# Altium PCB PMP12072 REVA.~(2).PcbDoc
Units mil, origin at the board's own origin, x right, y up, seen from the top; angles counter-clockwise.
Board outline 4950 x 3450 mil, 2 copper layers (Top Layer, Bottom Layer), stack 62 mil thick; 20 components, 17 nets, 97 pads, 14 vias.
Unrouted connection lines stored in the file: 46.
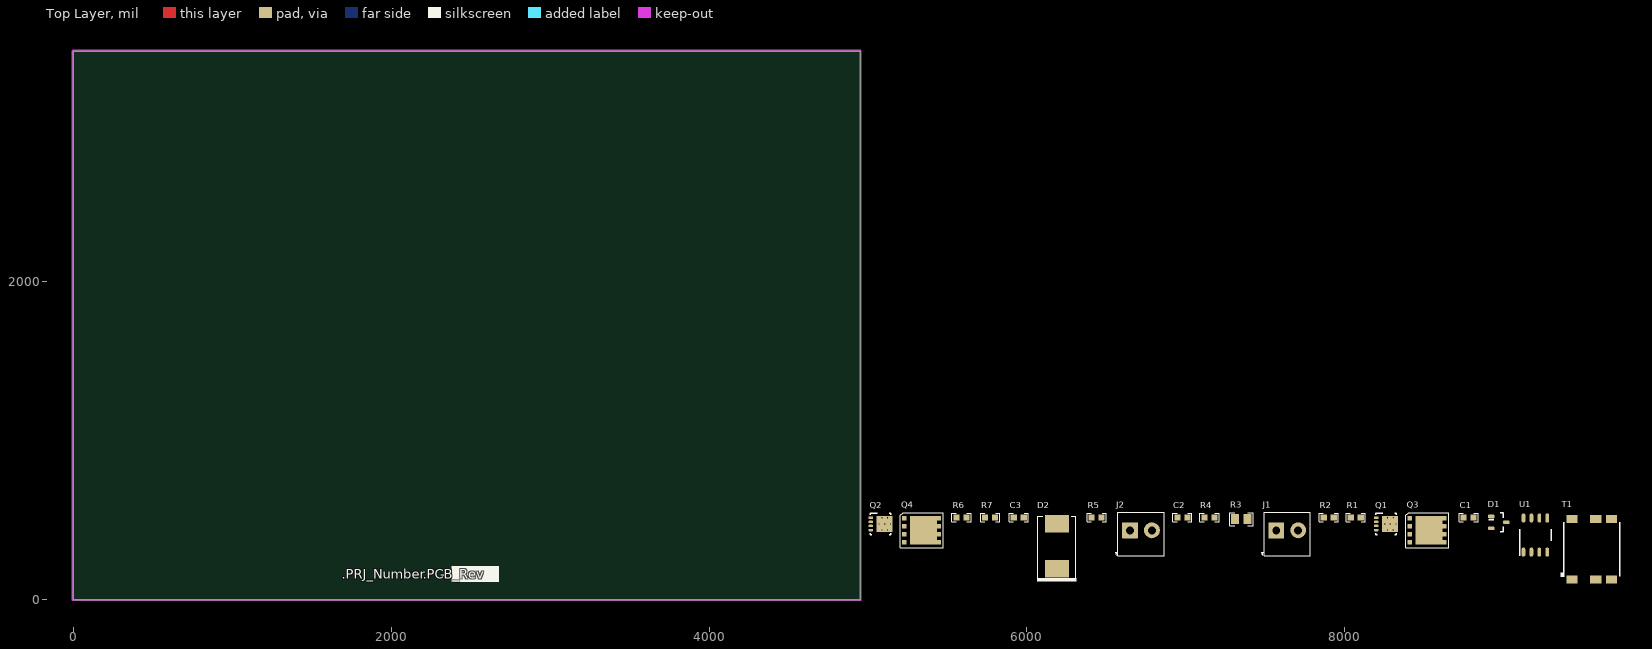
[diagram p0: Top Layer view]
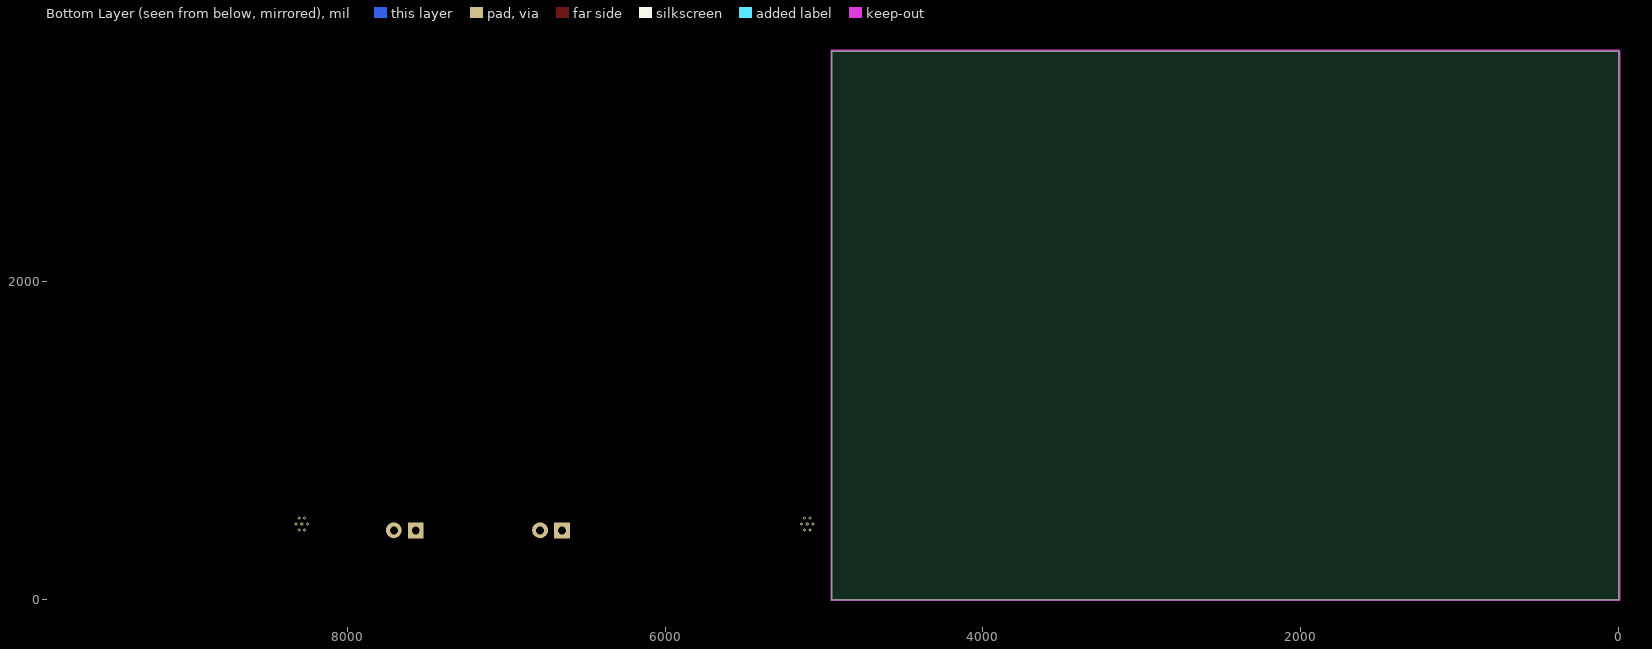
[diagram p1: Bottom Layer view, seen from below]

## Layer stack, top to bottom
Top Solder: solder mask 0.4, Solder Resist, Dk 3.5
Top Layer: signal copper 1.4
Dielectric1: core 59.2, FR-4, Dk 4.8
Bottom Layer: signal copper 1.4
Bottom Solder: solder mask 0.4, Solder Resist, Dk 3.5

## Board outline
0,0 4950,0 4950,3450 0,3450

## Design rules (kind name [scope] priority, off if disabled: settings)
AcuteAngle [All] p1: minimum=4.50000000000000E+0001 checktracksonly=FALSE
AssemblyTestPointUsage [All] p1: valid=2
Clearance Clearance_BoardEdge_MountingHoles [OnCopper and InComponentClass('Mounting Holes') vs IsKeepOut] p1: gap=40
Clearance Clearance_BoardEdge_Poly [OnCopper and InPoly vs IsKeepOut] p2: gap=25
Clearance Clearance_BoardEdge [OnCopper and Not InComponentClass('Logo') and not InComponentClass('FiducialMark') and not InRegion(1000,500,4000,800) and Not IsKeepout vs IsKeepOut] p3: gap=75
Clearance Clearance_Poly [InPolygon] p4: gap=25
Clearance [All] p5: gap=7.87
ComponentClearance ComponentClearance_Shunt [InComponentClass('Header') vs InComponentClass('Shunt')] p1: gap=0 collisioncheckmode=3 verticalgap=0 showdistances=FALSE
ComponentClearance ComponentClearance_MountingHoles_FiducialMarks [InComponentClass('Mounting Holes') vs InComponentClass('FiducialMark')] p2: gap=50 collisioncheckmode=3 verticalgap=10 showdistances=FALSE
ComponentClearance ComponentClearance_Logo [InComponentClass('Logo')] p3: gap=50 collisioncheckmode=3 verticalgap=10 showdistances=FALSE
ComponentClearance ComponentClearance_ScrewToNut [(HasFootprint('NY PMS 440 0025 PH')) vs (HasFootprint('Keystone_1902C'))] p4: gap=5 collisioncheckmode=3 verticalgap=10 showdistances=FALSE
ComponentClearance ComponentClearance_MountingHoles [InComponentClass('Mounting Holes')] p5: gap=250 collisioncheckmode=3 verticalgap=100000 showdistances=FALSE
ComponentClearance ComponentClearance_SmallPassives [HasFootprint('0201*') or HasFootprint('0402*') or HasFootprint('0508') or HasFootprint('0603*') or HasFootprint('0612') or HasFootprint('0805*') or HasFootprint('0815*') or HasFootprint('0830*') or HasFootprint('1206*') or HasFootprint('1210*') or HasFootprint('1808*') or HasFootprint('1812*') or HasFootprint('1825*') or HasFootprint('2010*') or HasFootprint('2220*') or HasFootprint('2225*') or HasFootprint('2512*') or HasFootprint('2728*') or HasFootprint('3518*') vs HasFootprint('0201*') or HasFootprint('0402*') or HasFootprint('0508') or HasFootprint('0603*') or HasFootprint('0612') or HasFootprint('0805*') or HasFootprint('0815*') or HasFootprint('0830*') or HasFootprint('1206*') or HasFootprint('1210*') or HasFootprint('1808*') or HasFootprint('1812*') or HasFootprint('1825*') or HasFootprint('2010*') or HasFootprint('2220*') or HasFootprint('2225*') or HasFootprint('2512*') or HasFootprint('2728*') or HasFootprint('3518*')] p6: gap=20 collisioncheckmode=3 verticalgap=10 showdistances=FALSE
ComponentClearance ComponentClearance_THtoSMT [IsThruComponent vs IsSMTComponent] p7: gap=100 collisioncheckmode=3 verticalgap=30 showdistances=FALSE
ComponentClearance ComponentClearance_THtoTH [IsThruComponent vs IsThruComponent] p8: gap=118.11 collisioncheckmode=3 verticalgap=30 showdistances=FALSE
ComponentClearance [All] p9: gap=40 collisioncheckmode=3 verticalgap=10 showdistances=FALSE
DiffPairsRouting [All] p1: maxlimit=100 minlimit=10 mostfreqgap=10 toplayer_minwidth=15 toplayer_maxwidth=15 toplayer_prefwidth=15 bottomlayer_minwidth=15 bottomlayer_maxwidth=15 bottomlayer_prefwidth=15 maxuncoupledlength=1000
FabricationTestPointUsage TestPointUsage [All] p1: valid=2 allowmultiple=FALSE
FabricationTestpoint Testpoint [All] p1: side=3 testpointundercomponent=TRUE minsize=40 maxsize=100 preferedsize=60 minholesize=0 maxholesize=40 preferedholesize=32 testpointgrid=1 allowsidetop=TRUE allowsidebottom=TRUE usegrid=TRUE gridtolerance=0.01
FanoutControl Fanout_LCC [IsLCC] p1: bgadir=Out bgaviamode=Centered fanoutstyle=Auto fanoutdirection=Alternating viagrid=1 // Fanout_LCC (Default Rule)
FanoutControl Fanout_BGA [IsBGA] p2: bgadir=Out bgaviamode=Centered fanoutstyle=Auto fanoutdirection=Alternating viagrid=1 // Fanout_BGA (Default Rule)
FanoutControl Fanout_Default [All] p4: bgadir=Out bgaviamode=Centered fanoutstyle=Auto fanoutdirection=Alternating viagrid=1 // Fanout_Default (Default Rule)
FanoutControl Fanout_Small [(CompPinCount < 5)] p5: bgadir=Out bgaviamode=Centered fanoutstyle=Auto fanoutdirection=OutThenIn viagrid=1 // Fanout_Small (Default Rule)
HoleSize [All] p1: absolutevalues=TRUE maxlimit=251 minlimit=8 maxpercent=80.000 minpercent=20.000
MinimumAnnularRing MinimumAnnularRing_ThermalPadVias [IsVia and InAnyComponent] p1: minimumring=5.91
MinimumAnnularRing [All] p2: minimumring=9
MinimumSolderMaskSliver MinimumSolderMaskSliver_Logo [InComponentClass('Logo') vs InComponentClass('Logo')] p1: minsoldermaskwidth=0.7
MinimumSolderMaskSliver [All] p2: minsoldermaskwidth=3.94
PlaneConnect [All] p1: planeconnectstyle=Relief reliefexpansion=10 reliefentries=4 reliefconductorwidth=10 reliefairgap=10
PolygonConnect [All] p1: connectstyle=Relief reliefconductorwidth=10 reliefentries=4 polygonreliefangle="90 Angle" airgapwidth=10
RoutingVias ThermalPadVias [IsVia and InAnyComponent] p1: holewidth=7.87 width=19.68 viastyle="Through Hole" minholewidth=7.87 minwidth=19.68 maxholewidth=12.99 maxwidth=23.62
RoutingVias [All] p2: holewidth=16 width=34 viastyle="Through Hole" minholewidth=7.87 minwidth=26 maxholewidth=40 maxwidth=65
SMDToCorner [All] p1: distance=30000
SilkToSilkClearance [All] p1: silktosilkclearance=5
SilkToSolderMaskClearance SilkscreenOverComponentPads [IsPad] p1: minsilkscreentomaskgap=5 clearancetoexposedcopper=TRUE
SolderMaskExpansion [All] p1: expansion=1.97
UnpouredPolygon [All] p1: allowunpoured=FALSE
Width [All] p1: maxlimit=100 minlimit=6 preferedwidth=10 checkconnectedcopper=TRUE
15 further rules are at their usual default settings.

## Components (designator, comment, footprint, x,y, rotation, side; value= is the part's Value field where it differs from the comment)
C1 "C1608X7R1H104K" 0603 8778,516 r0 top
C2 "C1608X7R1H103K" 0603 6978,516 r0 top
C3 "C1608X5R1C105K" 0603 5948,516 r0 top
D1 "BAT54C" SOT-23 8968,486 r0 top
D2 "SMCJ48CA" SMC 6188,336 r90 top
J1 "ED555/2DS" TERM_BLK_ED555-2DS 7568,436 r0 top
J2 "ED555/2DS" TERM_BLK_ED555-2DS 6648,436 r0 top
Q1 "CSD19538Q3A" DNH0008A 8258,476 r0 top
Q2 "CSD19538Q3A" DNH0008A 5078,476 r0 top
Q3 "ALT" TRANS_NexFET_Q5A 8518,436 r0 top
Q4 "ALT" TRANS_NexFET_Q5A 5338,436 r0 top
R1 "CRCW060310K0FKEA" 0603 8068,516 r0 top
R2 "CRCW06033R30JNEA" 0603 7898,516 r0 top
R3 "CRCW0805301RFKEA" 0805_HV 7348,506 r0 top
R4 "CRCW0603100KFKEA" 0603 7148,516 r0 top
R5 "CRCW06031K00FKEA" 0603 6438,516 r0 top
R6 "CRCW060320K0FKEA" 0603 5588,516 r0 top
R7 "CRCW060380K6FKEA" 0603 5768,516 r0 top
T1 "PA0173NLT" PULSE_PA0173 9568,316 r90 top
U1 "UCC28086D" D0008A_N 9198,406 r90 top

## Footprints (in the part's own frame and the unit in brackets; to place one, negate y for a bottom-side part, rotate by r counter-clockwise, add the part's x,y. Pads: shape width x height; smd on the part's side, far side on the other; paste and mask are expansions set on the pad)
0603 [mm] "0603 from SM-752 data"
  rect 1x0.95 smd: 1(-0.8,0) 2(0.8,0)
  silkscreen extent -1.52,-0.69 1.52,0.69, body extent -0.87,-0.47 0.87,0.47, height 1
0805_HV [mil] "0805 with 30mil clearance between pads"
  rect 50x63 smd: 1(-40,0) 2(40,0)
  silkscreen extent -74,-40 74,40, body extent -43,-29 43,29, height 57
D0008A_N [mm] "SOIC, 8-Leads, Body 4.9x3.9mm, Pitch 1.27mm, IPC Medium Density"
  oval 1.45x0.6 smd: 1(-2.725,1.905) 2(-2.725,0.635) 3(-2.725,-0.635) 4(-2.725,-1.905) 5(2.725,-1.905) 6(2.725,-0.635) 7(2.725,0.635) 8(2.725,1.905)
  silkscreen extent -3.3,-2.5 0.9,2.5, body extent -3,-2.45 3,2.45, height 1.63
DNH0008A [mm] "8 pin VSONP, 0.65 mm pitch"
  rrect50% 0.7x0.4 smd paste-0.05 mask-0.05: 1(-1.55,0.975) 2(-1.55,0.325) 3(-1.55,-0.325) 4(-1.55,-0.975) 5(1.55,-0.975) 6(1.55,-0.325) 7(1.55,0.325) 8(1.55,0.975)
  rrect14% 0.705x1.125 on Top Paste: 9(-0.208,-0.663) 9(-0.208,0.662) 9(0.697,-0.663) 9(0.697,0.662)
  rrect6% 1.775x2.45 on Top Solder: 9(0.327,0)
  rrect4% 2.51x2.55 smd paste-1.5 mask-1.5: 9(0.645,0)
  rect 0.5x0.3 on Top Solder: 9(1.175,-0.975) 9(1.175,-0.325) 9(1.175,0.325) 9(1.175,0.975)
  silkscreen extent -1.62,-1.7 1.62,1.7, body extent -1.65,-1.65 1.65,1.66, height 0.91
PULSE_PA0173 [mil] "PULSE"
  rect 50x70 smd: 1(-190,140) 2(-190,-10) 3(-190,-110) 4(190,-110) 5(190,-10) 6(190,140)
  silkscreen extent -175,-160 170,211, body extent -235,-160 235,190, height 160
SMC [mil] "Molded Diode, 2-Leads, Body 6.9x5.8mm, IPC Medium Density, based on OnSemi component dimensions and land patterns"
  rect 110x150 smd: 1(-140.49,0) 2(140.49,0)
  silkscreen extent -221,-124 189,123, body extent -156,-116 156,116, height 91
SOT-23 [mm] "SOT23, 3-Leads, Body 2.9x1.3mm, Pitch 0.95mm, Lead Span 2.5mm, IPC Medium Density"
  rrect50% 1x0.6 smd: 1(-1.2,0.95) 2(-1.2,-0.95) 3(1.2,0)
  silkscreen extent -1.63,-1.5 0.7,1.5, body extent -1.16,-1.45 1.21,1.45, height 1
TERM_BLK_ED555-2DS [mil]
  rrect4% 100x100 hole 50: 1(0,0)
  round 100 hole 50: 2(138,0)
  silkscreen extent -93,-161 215,113, body extent -69,-150 207,106, height 323
TRANS_NexFET_Q5A [mm] "TI recommended land pattern (nominal) M0139-01"
  rect 0.75x0.675 smd paste-0.1 mask+0.051: 1(-2.776,1.917) 2(-2.776,0.639) 3(-2.776,-0.639) 4(-2.776,-1.917)
  rect 0.655x0.675 smd paste-0.1 mask+0.051: 5(2.776,-1.917) 6(2.776,-0.639) 7(2.776,0.639) 8(2.776,1.917)
  rect 4.295x4.51 smd paste-2.2 mask+0.051: 9(0.301,0)
  silkscreen extent -3.4,-2.8 3.4,2.8, body extent -3.05,-2.5 3.05,2.5, height 1.11

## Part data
C1: "CAP, CERM, 0.1uF, 50V, +/-10%, X7R, 0603"
C2: "CAP, CERM, 0.01uF, 50V, +/-10%, X7R, 0603"
C3: "CAP, CERM, 1uF, 16V, +/-10%, X5R, 0603"
D1: library part BAT54C-7-F, "Diode, Schottky, 30V, 0.2A, SOT-23"
D2: library part SMCJ33CA, "Diode, TVS, Bi, 48V, 1500W, SMC"
J1 J2: "Terminal Block, 6A, 3.5mm Pitch, 2-Pos, TH"
Q1 Q2: "MOSFET, N-CH, 100 V, 5 A, DNH0008A"
Q3 Q4: library part CSD19534Q5A, "MOSFET, SON 5x6mm"
R1: "RES, 10.0 k, 1%, 0.1 W, 0603"
R2: "RES, 3.3 ohm, 5%, 0.1W, 0603"
R3: "RES, 301 ohm, 1%, 0.125W, 0805"
R4: "RES, 100k ohm, 1%, 0.1W, 0603"
R5: "RES, 1.00 k, 1%, 0.1 W, 0603"
R6: "RES, 20.0 k, 1%, 0.1 W, 0603"
R7: "RES, 80.6 k, 1%, 0.1 W, 0603"
T1: "Transformer, Gate Drive, 980uH, SMT"
U1: "Push-Pull PWM Controller with Programmable Slope Compensation with Current Control, 50 % Duty Cycle, -40 to +85 degC, 8-pin SOIC (D), Green (RoHS & no Sb/Br)"

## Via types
v1: diameter 19.68, hole 7.87, Top Layer to Bottom Layer, 14 vias

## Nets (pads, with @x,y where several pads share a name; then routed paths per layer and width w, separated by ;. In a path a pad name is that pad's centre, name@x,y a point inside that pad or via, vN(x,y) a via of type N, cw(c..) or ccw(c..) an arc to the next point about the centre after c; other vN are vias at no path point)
GND: C3.1 J1.2 R5.2 R6.2 R7.2 U1.5
NetC1_1: C1.1 U1.6
NetC1_2: C1.2 T1.1
NetC2_1: C2.1 D1.3 R2.2 R4.2
NetC2_2: C2.2 Q1.1 Q1.2 Q1.3 Q2.1 Q2.2 Q2.3 Q3.1 Q3.2 Q3.3 Q4.1 Q4.2 Q4.3 R4.1 T1.3 T1.5
NetC3_2: C3.2 R1.2 R3.2 U1.8
NetD1_1: D1.1 T1.2
NetD1_2: D1.2 T1.4
NetD2_1: D2.1 J2.1 Q1.5 Q1.6 Q1.7 Q1.8 Q1.9@8283.39,476 Q3.5 Q3.6 Q3.7 Q3.8 Q3.9
  other v1: 8267.65,437.61 8303.28,437.61 8249.83,476 8285.46,476 8321.09,476 8267.65,514.39 8303.28,514.39
NetD2_2: D2.2 J2.2 Q2.5 Q2.6 Q2.7 Q2.8 Q2.9@5103.39,476 Q4.5 Q4.6 Q4.7 Q4.8 Q4.9
  other v1: 5087.65,437.61 5123.28,437.61 5069.83,476 5105.46,476 5141.09,476 5087.65,514.39 5123.28,514.39
NetJ1_1: J1.1 R3.1
NetQ1_4: Q1.4 Q2.4 Q3.4 Q4.4 R2.1
NetR1_1: R1.1 U1.1
NetR5_1: R5.1 U1.3
NetR6_1: R6.1 U1.2
NetR7_1: R7.1 U1.4
NetT1_6: T1.6 U1.7
pads on no net: Q1.9@8249.83,449.92 Q1.9@8249.83,502.08 Q1.9@8270.89,476 Q1.9@8285.46,449.92 Q1.9@8285.46,502.08 Q1.9@8304.26,437.61 Q1.9@8304.26,463.2 Q1.9@8304.26,488.8 Q1.9@8304.26,514.39 Q2.9@5069.83,449.92 Q2.9@5069.83,502.08 Q2.9@5090.89,476 Q2.9@5105.46,449.92 Q2.9@5105.46,502.08 Q2.9@5124.26,437.61 Q2.9@5124.26,463.2 Q2.9@5124.26,488.8 Q2.9@5124.26,514.39

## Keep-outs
Keep-Out Layer:
  lines w10: -5,0 ccw(c0,0) 0,-5 ; -5,0 ccw(c0,0) 0,-5 ; -5,0 ccw(c0,0) 0,-5 ; -5,0 ccw(c0,0) 0,-5 ; -5,0 ccw(c0,0) 0,-5 ; -5,0 ccw(c0,0) 0,-5 ; -5,0 -5,3450 ; -5,3450 cw(c0,3450) 0,3455 ; -5,3450 cw(c0,3450) 0,3455 ; -5,3450 cw(c0,3450) 0,3455 ; -5,3450 cw(c0,3450) 0,3455 ; -5,3450 cw(c0,3450) 0,3455 ; -5,3450 cw(c0,3450) 0,3455 ; 0,-5 4950,-5 ; 0,3455 4950,3455 ; 4950,-5 ccw(c4950,0) 4955,0 ; 4950,-5 ccw(c4950,0) 4955,0 ; 4950,-5 ccw(c4950,0) 4955,0 ; 4950,-5 ccw(c4950,0) 4955,0 ; 4950,-5 ccw(c4950,0) 4955,0 ; 4950,-5 ccw(c4950,0) 4955,0 ; 4950,3455 cw(c4950,3450) 4955,3450 ; 4950,3455 cw(c4950,3450) 4955,3450 ; 4950,3455 cw(c4950,3450) 4955,3450 ; 4950,3455 cw(c4950,3450) 4955,3450 ; 4950,3455 cw(c4950,3450) 4955,3450 ; 4950,3455 cw(c4950,3450) 4955,3450 ; 4955,0 4955,3450
  text ".Layer_Name" at 577,-858.49 h60

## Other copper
Top Layer:
  text ".Layer_Name" at 577,-858.49 h60
Bottom Layer:
  text ".Layer_Name" at 577,-858.49 h60

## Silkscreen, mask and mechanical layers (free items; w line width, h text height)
Top Overlay:
  region: 2680,210 2380,210 2380,110 2680,110
  text ".PRJ_Number" at 1690,130 h60
  text ".PCB_Rev" at 2200,130.01 h60
  text "-" at 2310,130.01 h60
  text ".Layer_Name" at 577,-858.49 h60
Bottom Overlay:
  text ".Layer_Name" at 577,-858.49 h60
Top Paste:
  text ".Layer_Name" at 577,-858.49 h60
Bottom Paste:
  text ".Layer_Name" at 577,-858.49 h60
Top Solder:
  text ".Layer_Name" at 577,-858.49 h60
  text ".Layer_Name" at 577,-858.49 h60
Bottom Solder:
  text ".Layer_Name" at 577,-858.49 h60
Drill Guide:
  text ".Layer_Name" at 577,-858.49 h60
M1 Board Outline:
  the board outline again, w10
  text ".Layer_Name" at 577,-858.49 h60
M2 Board Dimensions:
  rectangle: 125,-410.5 500,-285.5
  rectangle: 0,-285.5 125,-160.5
  lines w7: 0,-285.5 1000,-285.5 ; 125,-410.5 125,-160.5 ; 250,-410.5 250,-160.5 ; 500,-410.5 500,-160.5 ; 750,-410.5 750,-160.5 ; 0,-410.5 0,-160.5 1000,-160.5 1000,-410.5 0,-410.5
  text ".Layer_Name" at 577,-858.49 h60
M3 3D STEP Top:
  text ".Layer_Name" at 577,-858.49 h60
M4 3D STEP Bottom:
  text ".Layer_Name" at 577,-858.49 h60
M5 Assembly Top:
  lines w10: -292,-930.17 6308,-930.17 ; -292,-726.83 6310,-726.83 ; -292,-523.5 -292,-1133.5 3713,-1133.5 6310,-1133.5 6310,-523.5 -291.5,-523.5 -291.5,-1133.5 1284,-1133.5 ; 2173,-1133.5 2173,-523.5 ; 3440,-726.83 3440,-523.5 ; 4280,-726.83 4280,-523.5 ; 4902,-1140 4902,-937.17
  text "COMPONENTS MARKED 'DNP' SHOULD NOT BE POPULATED." at 1153.5,-318.5 h60
  text "ASSEMBLY VARIANT:" at 1153,-434 h60
  text ".VariantName" at 2189,-434 h60
  text "PCB VIEWED FROM TOP SIDE" at -228.5,-655.67 h60
  text "BOARD #:" at 2248,-655.67 h60
  text ".PRJ_Number" at 2793.5,-655.67 h60
  text "REV:" at 3638,-655.67 h60
  text ".PCB_Rev" at 3929.5,-655.67 h60
  text "SVN REV:" at 4476,-655.67 h60
  text ".VersionControl_RevNumber" at 4982,-655.67 h60
  text "IGNORE ->" at -228.5,-858.49 h60
  text "PLOT NAME =" at -228.5,-1064.34 h60
  text ".plot_File_Name" at 577,-1064.34 h60
  text "GENERATED    :" at 2250,-1064.34 h60
  text ".Print_Date" at 3119.5,-1064.34 h60
  text ".Print_Time" at 3848.5,-1064.34 h60
  text "TEXAS INSTRUMENTS" at 5113,-1064.34 h60
M6 Assembly Bottom:
  lines w10: -292.5,-727.33 6309.5,-727.33 ; -290.5,-930.67 6309.5,-930.67 ; 1115.5,-1140.5 1115.5,-937.67 ; 1737.5,-727.33 1737.5,-524 ; 2577.5,-727.33 2577.5,-524 ; 3844.5,-1134 3844.5,-524 ; 4733.5,-1134 6309,-1134 6309,-524 -292.5,-524 -292.5,-1134 2304.5,-1134 6309.5,-1134 6309.5,-524
  text "COMPONENTS MARKED 'DNP' SHOULD NOT BE POPULATED." at 6102,-318 h60
  text ".VariantName" at 5058,-434 h60
  text "ASSEMBLY VARIANT:" at 6097,-434 h60
  text ".VersionControl_RevNumber" at 1035.5,-656.17 h60
  text "SVN REV:" at 1541.5,-656.17 h60
  text ".PCB_Rev" at 2088,-656.17 h60
  text "REV:" at 2379.5,-656.17 h60
  text ".PRJ_Number" at 3224,-656.17 h60
  text "BOARD #:" at 3769.5,-656.17 h60
  text "PCB VIEWED FROM BOTTOM SIDE" at 6246,-656.17 h60
  text "IGNORE ->" at 2547.85,-858.49 h60
  text "TEXAS INSTRUMENTS" at 904.5,-1064.84 h60
  text ".Print_Time" at 2169,-1064.84 h60
  text ".Print_Date" at 2898,-1064.84 h60
  text "GENERATED    :" at 3767.5,-1064.84 h60
  text ".plot_File_Name" at 5440.5,-1064.84 h60
  text "PLOT NAME =" at 6246,-1064.84 h60
M9 Title Sheet:
  drawing of 57 lines, arcs and shapes, not listed
  text "1" at 739.84,8036.5 h70
  text "2" at 3235.5,8036.5 h70
  text "3" at 5724.84,8036.5 h70
  text "4" at 8231.51,8036.5 h70
  text "5" at 10730.5,8036.5 h70
  text "6" at 13235.5,8036.5 h70
  text "A" at -416.5,6893.5 h70
  text "A" at 14383.5,6893.5 h70
  text "B" at -416.5,4513.5 h70
  text "B" at 14383.5,4513.5 h70
  text "C" at -416.5,2138.5 h70
  text "C" at 14383.5,2138.5 h70
  text "PROJECT TITLE:" at 11343.5,277.5 h45
  text ".PRJ_Title" at 11393.5,144.17 h70
  text "DESIGNED FOR:" at 11343.5,-23.5 h45
  text ".PRJ_Customer" at 11393.5,-163.5 h70
  text "D" at -416.5,-231.5 h70
  text "D" at 14383.5,-231.5 h70
  text "FILE NAME:" at 11343.5,-323.5 h45
  text ".PCB_File_Name_No_Path" at 11393.5,-443.5 h70
  text "Texas Instruments (TI) and/or its licensors do not warrant the accuracy or completeness of this specification" at 6374,-605.34 h45
  text "ENGINEER:" at 11343.5,-613.5 h45
  text "LAYOUT BY:" at 12848.5,-613.5 h45
  text "or any information contained therein. TI and/or its licensors do not warrant that this design will meet" at 6329.01,-718 h45
  text ".PRJ_Engineer" at 11393.5,-768.49 h70
  text ".PCB_Layout" at 12899,-768.49 h70
  text "the specifications, will be suitable for your application or fit for any particular purpose, or will operate in" at 6329.01,-830.67 h45
  text ".Layer_Name" at 577,-858.49 h60
  text "ALTIUM DESIGNER VERSION:" at 12848.5,-923.5 h45
  text "an implementation. TI and/or its licensors do not warrant that the design is production worthy. You should" at 6329.01,-943.33 h45
  text "completely validate and test your design implementation to confirm the system functionality for your application." at 6374,-1056 h45
  text ".print_Scale" at 11393.5,-1056.83 h70
  text ".Application_BuildNumber" at 12899,-1056.83 h70
  text "1" at 739.84,-1263.5 h70
  text "2" at 3235.5,-1263.5 h70
  text "3" at 5724.84,-1263.5 h70
  text "4" at 8231.51,-1263.5 h70
  text "5" at 10730.5,-1263.5 h70
  text "6" at 13235.5,-1263.5 h70
M10 Fab Notes:
  drawing of 185 lines, arcs and shapes, not listed
  text "DESIGN INFORMATION" at 12381.02,5910 h60
  text "MIN. TRACK WIDTH:" at 11736.46,5730 h60
  text "8" at 12832.7,5730 h60
  text "MIL" at 12987.46,5730 h60
  text "MIN. CLEARANCE:" at 11736.46,5598 h60
  text "0.2" at 12772.7,5598 h60
  text "mm" at 12987.46,5598 h60
  text "MIN. VIA PAD SIZE:" at 11736.46,5466 h60
  text "24" at 12802.71,5466 h60
  text "MIL" at 12987.46,5466 h60
  text "0.05mm (2MIL)" at 12431.46,5324.29 h60
  text "MINIMUM ANNULAR RING" at 11407.23,5320 h60
  text "EXTERNAL" at 13139.46,5320 h60
  text "PER" at 11607.23,5202 h60
  text "IPC-D-275 CLASS 2 LEVEL C" at 11827.23,5202 h60
  text "MIL, HOLES" at 13315.46,5089.71 h60
  text "+/-" at 12923,5089 h60
  text "+/-" at 13777,5089 h60
  text "REGISTRATION TOLERANCES:" at 11407.23,5084 h60
  text "METAL" at 12607,5084 h60
  text "5" at 13183.2,5084 h60
  text "3" at 14016.2,5084 h60
  text "MIL" at 14132.46,5084 h60
  text "MATERIAL:" at 11332.46,4874.54 h60
  text "FR-4 High Tg" at 12318.9,4734.21 h60
  text "FR-408" at 11753.46,4725.64 h60
  text "X" at 12165.46,4725.64 h60
  text "OTHER" at 13241.46,4725.64 h60
  text "62 MIL (1.6mm) +/-10%" at 12073.56,4562.92 h60
  text "THICKNESS:" at 11407.23,4558.64 h60
  text "X" at 11945.4,4558.64 h60
  text "OTHER" at 13358.46,4558.64 h60
  text "TOLERANCE:" at 11407.23,4400.64 h60
  text "X" at 12246.53,4400.64 h60
  text "ANSI IPC-6012 TYPE 3 CLASS 2" at 12433.48,4400.64 h60
  text "OTHER +/-" at 12433.46,4244.64 h60
  text "BOW & TWIST:" at 11407.23,4087.64 h60
  text "X" at 12246.53,4087.64 h60
  text "ANSI IPC-6012 TYPE 3 CLASS 2" at 12433.48,4087.64 h60
  text "OTHER +/-" at 12433.46,3929.13 h60
  text "DRILLING:" at 11332.46,3790.64 h60
  text "REFERENCE:" at 11407.23,3673.64 h60
  text "X" at 12055.46,3673.64 h60
  text "AS SHOWN" at 12242.46,3673.64 h60
  text "X" at 12956.46,3673.64 h60
  text "NC_DRILL FILES" at 13093.46,3673.64 h60
  text "PTH MIN COPPER THICKNESS:" at 11407.23,3515.64 h60
  text "X" at 12757.46,3515.64 h60
  text "1MIL" at 12894.46,3515.64 h60
  text "OTHER" at 13391.46,3515.64 h60
  text "BOARD FINISH:" at 11332.46,3356.64 h60
  text "SILKSCREEN:" at 11487.68,3238.64 h60
  text "X" at 12436.46,3238.64 h60
  text "TOP" at 12562.46,3238.64 h60
  text "X" at 12946.46,3238.64 h60
  text "BOTTOM" at 13073.46,3238.64 h60
  text "SILKSCREEN COLOR:" at 11487.68,3071.64 h60
  text "X" at 12435.42,3071.64 h60
  text "WHITE" at 12562.46,3071.64 h60
  text "OTHER" at 13073.46,3071.64 h60
  text "SOLDER RESIST COLOR:" at 11487.68,2901.64 h60
  text "X" at 12055.42,2742.44 h60
  text "GREEN" at 12182.46,2742.44 h60
  text "BLUE" at 12773.46,2742.44 h60
  text "OTHER" at 13311.46,2742.44 h60
  text "IMMERSION GOLD (ENIG)" at 12393.46,2553.92 h60
  text "ENEPIG" at 13731,2550.64 h60
  text "SURFACE FINISH:" at 11332.46,2549.64 h60
  text "X" at 12206.51,2549.64 h60
  text "IMM. TIN/SILVER OR EQUIV" at 11662,2392.64 h60
  text "OTHER" at 13093.46,2392.64 h60
  text "ARRAY/PANEL:" at 11332.46,2213.64 h60
  text "CUT AND TRIM PER MECH LAYER 1" at 12393.46,2209.35 h60
  text "N.C. ROUTE" at 12393.46,2057.64 h60
  text "X" at 13072.46,2057.64 h60
  text "V. SCORE" at 13259.46,2057.64 h60
  text "CERTIFICATION:" at 11332.46,1920.64 h60
  text "MATERIALS AND WORKMANSHIP FOR ALL PCBS" at 12057.46,1920.64 h60
  text "TO MEET OR EXCEED THE REQUIREMENTS OF:" at 12057.46,1822.64 h60
  text "X" at 11683.96,1686.13 h60
  text "ANSI IPC-A-600F CLASS ->" at 11822.96,1686.13 h60
  text "X" at 13462.02,1686.13 h60
  text "2" at 13580.96,1686.14 h60
  text "1" at 13265.96,1684.64 h60
  text "3" at 13934.96,1684.64 h60
  text "X" at 11686.02,1526.64 h60
  text "UL 94V-0" at 11822.96,1526.64 h60
  text "X" at 12498.02,1526.64 h60
  text "RoHS" at 12634.96,1526.64 h60
  text "OTHER" at 13279.36,1526.64 h60
  text "PER ORDER" at 13676.42,1526.64 h60
  text "ADDITIONAL REQUIREMENTS:" at 11332.46,1385.64 h60
  text "MICROSECTION:" at 11407.23,1270.64 h60
  text "YES" at 12312.96,1270.64 h60
  text "REQUIRED" at 13174.46,1114.49 h60
  text "BARE BOARD ELEC. TEST:" at 11407.23,1111.64 h60
  text "NONE" at 12712.96,1111.64 h60
  text "X" at 13047.46,1111.64 h60
  text "PER ORDER" at 13766.46,1111.64 h60
  text "MANUFACTURER'S UL:" at 11407.23,954.64 h60
  text "RAIL" at 12572.96,950.35 h60
  text "METAL" at 13064.77,950.35 h60
  text "X" at 13440,950 h60
  text "SILK" at 13576.46,950.35 h60
  text ".Layer_Name" at 577,-858.49 h60
M11 Gerber Information:
  lines w10: -292,-930.17 6308,-930.17 ; -292,-726.83 6310,-726.83 ; -292,-523.5 -292,-1133.5 3713,-1133.5 6310,-1133.5 6310,-523.5 -291.5,-523.5 -291.5,-1133.5 1284,-1133.5 ; 2173,-1133.5 2173,-523.5 ; 3440,-726.83 3440,-523.5 ; 4280,-726.83 4280,-523.5 ; 4902,-1140 4902,-937.17
  text "ALL ARTWORK VIEWED FROM TOP SIDE" at -228.5,-655.67 h60
  text "BOARD #:" at 2248,-655.67 h60
  text ".PRJ_Number" at 2793.5,-655.67 h60
  text "REV:" at 3638,-655.67 h60
  text ".PCB_Rev" at 3929.5,-655.67 h60
  text "SVN REV:" at 4476,-655.67 h60
  text ".VersionControl_RevNumber" at 4982,-655.67 h60
  text "LAYER NAME =" at -228.5,-858.49 h60
  text "PLOT NAME =" at -228.5,-1064.34 h60
  text ".plot_File_Name" at 577,-1064.34 h60
  text "GENERATED    :" at 2250,-1064.34 h60
  text ".Print_Date" at 3119.5,-1064.34 h60
  text ".Print_Time" at 3848.5,-1064.34 h60
  text "TEXAS INSTRUMENTS" at 5113,-1064.34 h60
M12 Stackup:
  lines w6: 11360,7460 13910,7460 ; 11360,7564.4 13910,7564.4 ; 11300,6975 ccw(c11334,6975) 11334,6941 13936,6941 ccw(c13936,6975) 13970,6975 13970,7681 ccw(c13936,7681) 13936,7715 11334,7715 ccw(c11334,7681) 11300,7681 11300,6975
  text "The Stackup Legend below this is static." at 11605.5,7874.5 h60
  text "If you change the stackup, update the Legend." at 11615.5,7784.5 h60
  text "Layer Stack Up Detail for: Ref_Design.PcbDoc" at 11360,7597.1 h57
  text "Layer" at 11360,7525.4 h24
  text "Gerber" at 12255.81,7525.4 h24
  text "Copper" at 12819.33,7525.4 h24
  text "Dielectric" at 13422.04,7525.4 h24
  text "Name" at 11360,7477.4 h24
  text "Document" at 12255.81,7477.4 h24
  text "Thickness" at 12819.33,7477.4 h24
  text "Material" at 13422.04,7477.4 h24
  text "Top Solder Mask" at 11360,7384.44 h34
  text "(.GTS)" at 12255.81,7384.44 h34
  text "Solder Resist" at 13422.04,7384.44 h34
  text "Top Layer" at 11360,7287.69 h34
  text "(.GTL)" at 12255.81,7287.69 h34
  text "1.4mil" at 12819.33,7287.69 h34
  text "FR-4" at 13422.04,7239.31 h34
  text "Bottom Layer" at 11360,7190.94 h34
  text "(.GBL)" at 12255.81,7190.94 h34
  text "1.4mil" at 12819.33,7190.94 h34
  text "Bottom Solder Mask" at 11360,7094.19 h34
  text "(.GBS)" at 12255.81,7094.19 h34
  text "Solder Resist" at 13422.04,7094.19 h34
  text ".Layer_Name" at 577,-858.49 h60
M13 Component Bodies Top:
  text ".Layer_Name" at 577,-858.49 h60
M14 Component Bodies Bottom:
  text ".Layer_Name" at 577,-858.49 h60
M15 Courtyards Top:
  text ".Layer_Name" at 577,-858.49 h60
M16 Courtyards Bottom:
  text ".Layer_Name" at 577,-858.49 h60
Drill Drawing:
  text ".legend" at 5122.5,725.5 h60
  text "Drill Table" at 5147.5,540.5 h60
  text ".Layer_Name" at 577,-858.49 h60

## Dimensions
0,-410.5 to 1000,-410.5 on M2 Board Dimensions
0,0 to 4950,0 on M2 Board Dimensions
0,0 to 0,3450 on M2 Board Dimensions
